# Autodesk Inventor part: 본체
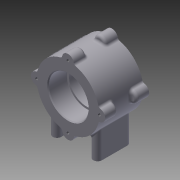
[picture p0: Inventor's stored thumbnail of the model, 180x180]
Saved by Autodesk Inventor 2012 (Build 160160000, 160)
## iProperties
Created: 2015-03
Part Number: 본체
Material: 알루미늄-6061
Document SubType Name: Modeling
Designer: narae
Density: 2.71 g/cm^3
Mass: 450.774 g
Surface Area: 332.747 cm^2
Volume: 166.337 cm^3
Author: narae
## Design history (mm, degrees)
sketch "스케치1"
  geometry: C1 r 37 at (0, 0); 1 further point
  constraints: 1 centre point, 1 coincident
  dimensions: "d0" = 74 diameter of C1
extrude "돌출1" new body sketch "스케치1" stored distance "d1" = 52; taper "d2" = 0 deg
sketch "스케치2"
  geometry: C1 r 7 at (0, 37); 1 further point
  constraints: 2 vertical alignment, 1 centre point, 1 other
  dimensions: "d3" = 14 diameter of C1
extrude "돌출2" join sketch "스케치2" distance "d4" = 15; taper "d5" = 0 deg
hole "구멍1" diameter "d8" = 3.242; stored, may be unused: countersink angle "d12" = 90 deg, drill point angle "d14" = 118 deg; dims "d6" = 10, "d7" = 10, "d9" = 8, "d10" = 4, "d11" = 2, "d13" = 11
hole "구멍2" diameter "d17" = 47; stored, may be unused: countersink angle "d21" = 90 deg, drill point angle "d23" = 0 deg; dims "d15" = 10, "d16" = 10, "d18" = 8, "d19" = 4, "d20" = 2, "d22" = 22
hole "구멍3" diameter "d26" = 47; stored, may be unused: countersink angle "d30" = 90 deg, drill point angle "d32" = 0 deg; dims "d24" = 10, "d25" = 10, "d27" = 8, "d28" = 4, "d29" = 2, "d31" = 22
hole "구멍4" diameter "d35" = 42; stored, may be unused: countersink angle "d39" = 90 deg, drill point angle "d41" = 0 deg; dims "d33" = 10, "d34" = 10, "d36" = 8, "d37" = 4, "d38" = 2, "d40" = 22
fillet "모깎기1" dims "d42" = 3, "d97" = 0.3
node "작업 평면1"
sketch "스케치3"
  geometry: L1 (-61.6, 0)-(61.6, 0) reference; L2 (0, 36.4)-(0, -36.4) reference; L3 (-29, -15)-(-29, 15); L4 (-19, -15)-(-19, 15); L5 (19, -15)-(19, 15); L6 (29, -15)-(29, 15); A1 r 5 centre (24, -15) between (19, -15) and (29, -15); A2 r 5 centre (24, 15) between (29, 15) and (19, 15); A3 r 5 centre (-24, -15) between (-29, -15) and (-19, -15); A4 r 5 centre (-24, 15) between (-19, 15) and (-29, 15); 1 further point
  constraints: 8 end point, 8 point on circle, 7 tangent, 4 centre point, 3 equal radius, 2 horizontal alignment, 2 symmetric about line, 2 vertical alignment, 1 parallel
  dimensions: "d47" = 10 diameter of A1; "d48" = 40 dimension on A2 A1; "d49" = 48 distance of A1.centre A3.centre
extrude "돌출3" join sketch "스케치3" stored distance "d50" = 15; taper "d51" = 0 deg
hole "구멍5" diameter "d54" = 4.134; stored, may be unused: countersink angle "d58" = 90 deg, drill point angle "d60" = 118 deg; dims "d52" = 10, "d53" = 10, "d55" = 6, "d56" = 4, "d57" = 2, "d59" = 8
hole "구멍7" diameter "d72" = 4.134; stored, may be unused: countersink angle "d76" = 90 deg, drill point angle "d78" = 118 deg; dims "d70" = 10, "d71" = 10, "d73" = 6, "d74" = 4, "d75" = 2, "d77" = 8
hole "구멍8" diameter "d81" = 4.134; stored, may be unused: countersink angle "d85" = 90 deg, drill point angle "d87" = 118 deg; dims "d79" = 10, "d80" = 10, "d82" = 6, "d83" = 4, "d84" = 2, "d86" = 8
hole "구멍9" diameter "d90" = 4.134; stored, may be unused: countersink angle "d94" = 90 deg, drill point angle "d96" = 118 deg; dims "d88" = 10, "d89" = 10, "d91" = 6, "d92" = 4, "d93" = 2, "d95" = 8
chamfer "모따기1" distance "d98" = 1; stored, may be unused: second distance "d99" = 2, angle "d100" = 45 deg
sketch "스케치5"
  geometry: L1 (0, 26)-(0, -26); L2 (24.5, 26)-(-24.5, 26) reference; 3 further points
  constraints: 3 coincident, 2 end point, 2 midpoint, 1 vertical
node "작업 평면7"
  node "작업 평면6"
sketch "스케치7"
  geometry: L1 (-26, -18.921)-(-26, 18.921) reference; 2 further points
  constraints: 1 coincident, 1 other
  dimensions: "d107" = 26 distance from line of L1 point (0, 0)
feature "엠보싱2" sketch "스케치7" dims "d108" = 0.5, "d109" = 0
fillet "모깎기2" dims "d110" = 3
node "솔리드1"
pattern_circular "원형 패턴1" dims "d44" = 360 deg
mirror "대칭1"
other parameters: "d46" = -56, "d106" = 45 deg
